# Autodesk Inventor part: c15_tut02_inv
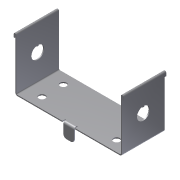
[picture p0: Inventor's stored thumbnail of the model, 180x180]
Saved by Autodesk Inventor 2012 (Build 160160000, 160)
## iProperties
Created: 2010-05
Part Number: c15_tut02_inv
Material: Default
Document SubType Name: Sheet Metal
Designer: CADSoft
Density: 1 g/cm^3
Sheet Metal Rule: Default_mm
Flat Pattern Width: 5.12619 cm
Flat Pattern Length: 20.3859 cm
Flat Pattern Area: 104.502 cm^2
Sheet Metal Width: 51.262 mm
Sheet Metal Length: 203.859 mm
Sheet Metal Area: 10450.224 mm^2
Author: CADSoft
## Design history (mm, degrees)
node "Face1"
  sketch "Sketch1"
    geometry: L1 (0, 0)-(100, 0); L2 (100, 0)-(100, 40); L3 (100, 40)-(0, 40); L4 (0, 40)-(0, 0)
    constraints: 8 end point, 2 parallel, 1 horizontal, 1 perpendicular
    dimensions: "d0" = 100 distance of L2.end L3.end; "d1" = 40 distance of L1.end L2.end
hole "Hole1" diameter "d5" = 6; stored, may be unused: countersink angle "d9" = 90 deg, drill point angle "d11" = 118 deg; dims "d3" = 15, "d4" = 10, "d6" = 6, "d7" = 4, "d8" = 2, "d10" = 1 (= Thickness)
pattern_linear "Rectangular Pattern1" dims "d14" = 70
node "Flange1"
node "Flange2"
feature "Hem1" dims "d38" = 1 (= BendReliefWidth), "d39" = 0.5 (= BendReliefDepth), "d40" = 2 (= MinimumRemnant), "d41" = 1 (= BendRadius), "d42" = 4 (= 4 x Thickness), "d43" = 0.5 (= 0.5 x Thickness), "d44" = 0.25 (= 0.5 x d43), "SeamGap" = 0.01, "Thickness" = 1 (derived)
feature "Hem2" dims "d45" = 1 (= BendReliefWidth), "d46" = 0.5 (= BendReliefDepth), "d47" = 2 (= MinimumRemnant), "d48" = 1 (= BendRadius), "d49" = 4 (= 4 x Thickness), "d50" = 0.5 (= 0.5 x Thickness), "d51" = 0.25 (= 0.5 x d50), "SeamGap" = 0.01, "Thickness" = 1 (derived)
sketch "Sketch6"
  geometry: L1 (0, 40)-(0, 0) reference; L2 (48, 0)-(0, 0) reference; 2 further points
  dimensions: "d52" = 25 distance from line of L1 point (25, 20); "d54" = 20 distance from line of point (25, 20) L2
feature "iFeature15:1" sketch "Sketch6"
sketch "Sketch8"
  geometry: 2 further points
feature "iFeature15:2" sketch "Sketch8"
node "Flange3"
feature "Corner Round1" dims "d78" = 3
body "Solid1"
face "Plate1" dims "Thickness" = 1 (derived)
sketch "Sketch2"
  geometry: L1 (0, -50)-(40, -50); L2 (40, -50)-(40, 0); 2 other entities
  constraints: 4 end point, 4 other
face "Plate2" dims "d18" = 1 (= BendReliefWidth), "d19" = 0.5 (= BendReliefDepth), "d20" = 2 (= MinimumRemnant), "d21" = 1 (= BendRadius), "d22" = 50, "d23" = 90 deg, "d24" = 1 (= BendRadius), "d25" = 4 (= CornerReliefSize), "d26" = 1 (= GapSize), "d27" = 1 (= JacobiRadiusSize), "SeamGap" = 0.01, "Thickness" = 1 (derived)
bend "Bend1" dims "d18" = 1 (= BendReliefWidth), "d19" = 0.5 (= BendReliefDepth), "d20" = 2 (= MinimumRemnant), "d21" = 1 (= BendRadius), "d22" = 50, "d23" = 90 deg, "d24" = 1 (= BendRadius), "SeamGap" = 0.01, "Thickness" = 1 (derived)
feature "Corner1" dims "d22" = 50, "d23" = 90 deg, "d25" = 4 (= CornerReliefSize), "d26" = 1 (= GapSize), "d27" = 1 (= JacobiRadiusSize)
sketch "Sketch3"
  geometry: L1 (0, -50)-(40, -50); L2 (40, -50)-(40, 0); 2 other entities
  constraints: 4 end point, 4 other
face "Plate3" dims "d28" = 1 (= BendReliefWidth), "d29" = 0.5 (= BendReliefDepth), "d30" = 2 (= MinimumRemnant), "d31" = 1 (= BendRadius), "d32" = 50, "d33" = 90 deg, "d34" = 1 (= BendRadius), "d35" = 4 (= CornerReliefSize), "d36" = 1 (= GapSize), "d37" = 1 (= JacobiRadiusSize), "SeamGap" = 0.01, "Thickness" = 1 (derived)
bend "Bend2" dims "d28" = 1 (= BendReliefWidth), "d29" = 0.5 (= BendReliefDepth), "d30" = 2 (= MinimumRemnant), "d31" = 1 (= BendRadius), "d32" = 50, "d33" = 90 deg, "d34" = 1 (= BendRadius), "SeamGap" = 0.01, "Thickness" = 1 (derived)
feature "Corner2" dims "d32" = 50, "d33" = 90 deg, "d35" = 4 (= CornerReliefSize), "d36" = 1 (= GapSize), "d37" = 1 (= JacobiRadiusSize)
sketch "Sketch9"
  geometry: L1 (-53, 0)-(-43, 0); L2 (-43, 0)-(-43, 13); L3 (-43, 13)-(-53, 13); L4 (-53, 13)-(-53, 0)
  constraints: 8 end point
face "Plate4" dims "d67" = 1 (= BendReliefWidth), "d68" = 0.5 (= BendReliefDepth), "d69" = 2 (= MinimumRemnant), "d70" = 1 (= BendRadius), "d71" = 10, "d72" = 13, "d73" = 90 deg, "d74" = 1 (= BendRadius), "d75" = 4 (= CornerReliefSize), "d76" = 1 (= GapSize), "d77" = 1 (= JacobiRadiusSize), "SeamGap" = 0.01, "Thickness" = 1 (derived)
bend "Bend3" dims "d67" = 1 (= BendReliefWidth), "d68" = 0.5 (= BendReliefDepth), "d69" = 2 (= MinimumRemnant), "d70" = 1 (= BendRadius), "d72" = 13, "d73" = 90 deg, "d74" = 1 (= BendRadius), "SeamGap" = 0.01, "Thickness" = 1 (derived)
feature "Corner3" dims "d72" = 13, "d73" = 90 deg, "d75" = 4 (= CornerReliefSize), "d76" = 1 (= GapSize), "d77" = 1 (= JacobiRadiusSize)
sketch "Sketch4"
  geometry: L1 (1, 0)-(0, 0); L2 (-0.5, 0)-(-0.5, -2.75); L3 (-0.5, -2.75)-(-1.5, -2.75); L4 (-1.5, -2.75)-(-1.5, 0); A1 r 0.25 centre (-0.25, 0) between (0, 0) and (-0.5, 0); A2 r 1.25 centre (-0.25, 0) between (1, 0) and (-1.5, 0)
  constraints: 8 end point, 4 point on circle
sketch "Sketch5"
  geometry: L1 (1, 0)-(0, 0); L2 (-0.5, 0)-(-0.5, -2.75); L3 (-0.5, -2.75)-(-1.5, -2.75); L4 (-1.5, -2.75)-(-1.5, 0); A1 r 0.25 centre (-0.25, 0) between (0, 0) and (-0.5, 0); A2 r 1.25 centre (-0.25, 0) between (1, 0) and (-1.5, 0)
  constraints: 8 end point, 4 point on circle
feature "Definition1"
other parameters: "BendRadius" = 1 (= Thickness), "BendReliefWidth" = 1 (= Thickness), "BendReliefDepth" = 0.5 (= 0.5 x Thickness), "CornerReliefSize" = 4 (= 4 x Thickness), "MinimumRemnant" = 2 (= 2 x Thickness), "TransitionRadius" = 1 (= BendRadius), "JacobiRadiusSize" = 1 (= BendRadius), "GapSize" = 1 (= Thickness), "d2" = 1 (= BendRadius), "d60" = 90 deg, "d66" = 270 deg, "BendRadius" = 1, "BendReliefDepth" = 0.5, "BendReliefWidth" = 1, "CornerReliefSize" = 4, "GapSize" = 1, "JacobiRadiusSize" = 1, "MinimumRemnant" = 2, "Thickness" = 1, "TransitionRadius" = 1
